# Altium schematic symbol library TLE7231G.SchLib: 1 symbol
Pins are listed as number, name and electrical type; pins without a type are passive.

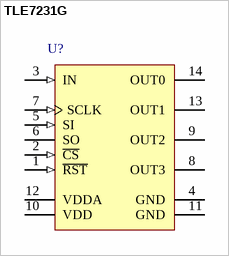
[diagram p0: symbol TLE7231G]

## TLE7231G
designator U?
SPIDER-4 Channel Low Side Driver, 10 uA Quiescent Current, 3 to 5.5 V VDD, -40 to 150 degC, PG-DSO-14-1, Reel, Green; Manufacturer: Infineon; PartNumber: TLE7231G; Channels: 4; Cranking mode: FALSE; Daisy-chain capability: TRUE; ID nom: 320 mA; ID(lim) (min): 0.5 A; Open Load Detection: off; Overcurrent limitation or shutdown: Shutdown; PWM Inputs: 1; Quiescent Current (max): 10 uA; RDS (on) (max): 2.2 Ohm; RDS (on) (typ): 1 Ohm; SPI: 8 Bit; VDD: 3 - 5.5 V; VDS(CL): 41 - 52 V
footprint INF-PG-DSO-14-1_N (SOP, 14-Leads, Body 8.65x3.9mm, Pitch 1.27mm, IPC Medium Density)
footprint INF-PG-DSO-14-1_L (SOP, 14-Leads, Body 8.65x3.9mm, Pitch 1.27mm, IPC High Density)
footprint INF-PG-DSO-14-1_M (SOP, 14-Leads, Body 8.65x3.9mm, Pitch 1.27mm, IPC Low Density)
pins: 1 ~{RST} (in) "Reset input pin; Digital input 3.3 V or 5V. Low active", 2 ~{CS} (in) "SPI chip select; Digital input 3.3 V or 5V. Low active", 3 IN (in) "Control Input; Digital input 3.3 V or 5V. In case of not used keep open.", 4 GND (power) "Ground; common ground for digital, analog and power", 5 SI (in) "Serial data in; Digital input 3.3 V or 5V.", 6 SO (hiz) "Serial data out; Digital input 3.3 V or 5V.", 7 SCLK (in) "Serial clock; Digital input 3.3 V or 5V.", 8 OUT3 (power) "Output Channel 3; Drain of power transistor channel 3", 9 OUT2 (power) "Output Channel 2; Drain of power transistor channel 2", 10 VDD (power) "Digital Supply Voltage; Connected to 5V Voltage with Reverse protection Diode and Filter against EMC", 11 GND (power) "Ground; common ground for digital, analog and power", 12 VDDA (power) "Analog Supply Voltage", 13 OUT1 (power) "Output Channel 1; Drain of power transistor channel 1", 14 OUT0 (power) "Output Channel 0; Drain of power transistor channel 0"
